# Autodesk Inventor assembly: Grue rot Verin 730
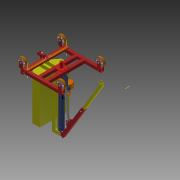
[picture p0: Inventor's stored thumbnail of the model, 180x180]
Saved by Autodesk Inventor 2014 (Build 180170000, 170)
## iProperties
Created: 2015-07
Part Number: Grue rot Verin 730
Document SubType Name: Assembly
Designer: OL
Author: OL
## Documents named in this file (29)
- D:\Lycée Larmand\Profs\SUJET BAC EDPI ETC\ELABORATION SUJET EDPI\Bourgeois RT 510\Modele Grue rotative\Grue rot Verin 730.iam
- D:\Lycée Larmand\Profs\SUJET BAC EDPI ETC\ELABORATION SUJET EDPI\Bourgeois RT 510\Modele Grue rotative\Cadre chariot.ipt
- D:\Lycée Larmand\Profs\SUJET BAC EDPI ETC\ELABORATION SUJET EDPI\Bourgeois RT 510\Modele Grue rotative\Axe.ipt
- D:\Lycée Larmand\Profs\SUJET BAC EDPI ETC\ELABORATION SUJET EDPI\Bourgeois RT 510\Modele Grue rotative\Poteau central.ipt
- D:\Lycée Larmand\Profs\SUJET BAC EDPI ETC\ELABORATION SUJET EDPI\Bourgeois RT 510\Modele Grue rotative\Potence pivot.ipt
- D:\Lycée Larmand\Profs\SUJET BAC EDPI ETC\ELABORATION SUJET EDPI\Bourgeois RT 510\Modele Grue rotative\Potence coulissante.ipt
- D:\Lycée Larmand\Profs\SUJET BAC EDPI ETC\ELABORATION SUJET EDPI\Bourgeois RT 510\Modele Grue rotative\Contrepoids.ipt
- D:\Lycée Larmand\Profs\SUJET BAC EDPI ETC\ELABORATION SUJET EDPI\Bourgeois RT 510\Modele Grue rotative\pompe\Pompe.ipt
- D:\Lycée Larmand\Profs\SUJET BAC EDPI ETC\ELABORATION SUJET EDPI\Bourgeois RT 510\Modele Grue rotative\Verin630-5-corps.ipt
- D:\Lycée Larmand\Profs\SUJET BAC EDPI ETC\ELABORATION SUJET EDPI\Bourgeois RT 510\Modele Grue rotative\Verin630-5-tige.ipt
- D:\Lycée Larmand\Profs\SUJET BAC EDPI ETC\ELABORATION SUJET EDPI\Bourgeois RT 510\Modele Grue rotative\Roue.ipt
- D:\Lycée Larmand\Profs\SUJET BAC EDPI ETC\ELABORATION SUJET EDPI\Bourgeois RT 510\Modele Grue rotative\Pivot de Direction.ipt
- D:\Lycée Larmand\Profs\SUJET BAC EDPI ETC\ELABORATION SUJET EDPI\Bourgeois RT 510\Modele Grue rotative\Palier de roue.ipt
- D:\Lycée Larmand\Profs\SUJET BAC EDPI ETC\ELABORATION SUJET EDPI\Bourgeois RT 510\Modele Grue rotative\Biellette.ipt
- D:\Lycée Larmand\Profs\SUJET BAC EDPI ETC\ELABORATION SUJET EDPI\Bourgeois RT 510\Modele Grue rotative\Vis H M10x20_02.ipt
- D:\Lycée Larmand\Profs\SUJET BAC EDPI ETC\ELABORATION SUJET EDPI\Bourgeois RT 510\Modele Grue rotative\Ecrou H M10x20_01.ipt
- D:\Lycée Larmand\Profs\SUJET BAC EDPI ETC\ELABORATION SUJET EDPI\Bourgeois RT 510\Modele Grue rotative\Axe D20.ipt
- D:\Lycée Larmand\Profs\SUJET BAC EDPI ETC\ELABORATION SUJET EDPI\Bourgeois RT 510\Modele Grue rotative\Goupille D20.ipt
- D:\Lycée Larmand\Profs\SUJET BAC EDPI ETC\ELABORATION SUJET EDPI\Bourgeois RT 510\Modele Grue rotative\Axe D20 L122.ipt
- D:\Lycée Larmand\Profs\SUJET BAC EDPI ETC\ELABORATION SUJET EDPI\Bourgeois RT 510\Modele Grue rotative\Rondelle d'appui D20.ipt
- D:\Lycée Larmand\Profs\SUJET BAC EDPI ETC\ELABORATION SUJET EDPI\Bourgeois RT 510\Modele Grue rotative\Axe D20 L96.ipt
- D:\Lycée Larmand\Profs\SUJET BAC EDPI ETC\ELABORATION SUJET EDPI\Bourgeois RT 510\Modele Grue rotative\Axe Roue D25 L116.ipt
- D:\Lycée Larmand\Profs\SUJET BAC EDPI ETC\ELABORATION SUJET EDPI\Bourgeois RT 510\Modele Grue rotative\Rondelle d'appui D25.ipt
- D:\Lycée Larmand\Profs\SUJET BAC EDPI ETC\ELABORATION SUJET EDPI\Bourgeois RT 510\Modele Grue rotative\Goupille D25.ipt
- D:\Lycée Larmand\Profs\SUJET BAC EDPI ETC\ELABORATION SUJET EDPI\Bourgeois RT 510\Modele Grue rotative\Butée manuelle.ipt
- D:\Lycée Larmand\Profs\SUJET BAC EDPI ETC\ELABORATION SUJET EDPI\Bourgeois RT 510\Modele Grue rotative\Goupille Cavalier.ipt
- D:\Lycée Larmand\Profs\SUJET BAC EDPI ETC\ELABORATION SUJET EDPI\Bourgeois RT 510\Modele Grue rotative\Bague d'arrêt D25.ipt
- D:\Lycée Larmand\Profs\SUJET BAC EDPI ETC\ELABORATION SUJET EDPI\Bourgeois RT 510\Modele Grue rotative\tuyau 1.ipt
- D:\Lycée Larmand\Profs\SUJET BAC EDPI ETC\ELABORATION SUJET EDPI\Bourgeois RT 510\Modele Grue rotative\tuyau 2.ipt
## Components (72 placed, 28 different names)
1. Cadre chariot:1 — Logement:1, Logement:9, Logement:10, Logement:12, Logement:13, Angle:1, Logement:37, Angle:12, Logement:38, Logement:39, Logement:42, Angle:15, Logement:43, Logement:44, Angle:16, Angle:17, Logement:54, Logement:74, Logement:75
2. Axe:1 — Logement:1, Logement:2
3. Poteau central:1 — Logement:2, Logement:3, Logement:4, Placage:3, Logement:5, Logement:6, Logement:7, Logement:21, Logement:22, Angle:3, Angle:6, Angle:7, Logement:27, Logement:28, Logement:57, Angle:20, Angle:22, Logement:58, Logement:60, Angle:24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
4. Potence pivot:1 — Logement:3, Placage:1, Placage:2, Placage:11, Logement:32, Angle:9, Logement:33, Logement:34, Logement:62, Angle:28
5. Potence coulissante:1 — Placage:1, Placage:2, Tangente:3
6. Contrepoids:1 — Logement:4, Placage:3, Angle:1, Angle:2, Logement:25, Logement:30, Logement:31
7. Pompe:1 — Logement:5, Logement:6, Logement:20, Logement:56, Angle:21, Angle:23, Logement:59, Logement:61, Angle:26, Angle:27, Logement:72
8. Verin630-5-corps:1 — Logement:7, Placage:4, Logement:73
9. Verin630-5-tige:1 — Placage:4, Placage:10
10. Roue:1 — Logement:9
11. Roue:2 — Logement:10
12. Pivot de Direction:1 — Logement:54, Logement:63, Angle:30, Angle:31, Placage:19, Placage:20
13. Palier de roue:1 — Logement:12, Logement:17, Logement:18, Placage:6, Angle:19, Logement:49, Logement:50, Logement:53, Placage:17, Angle:33
14. Palier de roue:2 — Logement:13, Logement:19, Angle:2, Placage:5, Logement:47, Angle:18, Logement:51, Logement:52, Logement:55, Placage:18, Angle:32
15. Biellette:1 — Logement:17, Placage:14, Logement:64, Logement:70
16. Biellette:2 — Logement:55, Placage:13, Logement:65, Logement:68
17. Roue:3 — Logement:18
18. Roue:4 — Logement:19
19. Vis H M10x20_02:1 — Logement:20, Angle:23
20. Ecrou H M10x20_01:1 — Logement:21, Angle:22
21. Axe D20:1 — Logement:22, Angle:3, Logement:23, Angle:4, Logement:24, Angle:5, Placage:24
22. Goupille D20:1 — Logement:24, Angle:5
23. Goupille D20:2 — Logement:23, Angle:4
24. Goupille D20:3 — Logement:26, Angle:7
25. Goupille D20:4 — Logement:29, Angle:8
26. Axe D20 L122:1 — Logement:25, Logement:26, Angle:6, Logement:29, Angle:8
27. Rondelle d'appui D20:1 — Logement:27
28. Rondelle d'appui D20:2 — Logement:28
29. Rondelle d'appui D20:3 — Logement:30
30. Rondelle d'appui D20:4 — Logement:31
31. Axe D20 L96:1 — Logement:32, Angle:9, Logement:35, Angle:10, Logement:36, Angle:11, Placage:23
32. Rondelle d'appui D20:5 — Logement:34
33. Rondelle d'appui D20:6 — Logement:33
34. Goupille D20:5 — Logement:35, Angle:10
35. Goupille D20:6 — Logement:36, Angle:11
36. Axe Roue D25 L116:1 — Logement:37, Angle:12, Angle:13, Angle:14
37. Rondelle d'appui D25:1 — Logement:38, Logement:41
38. Rondelle d'appui D25:2 — Logement:39, Logement:40
39. Goupille D25:1 — Logement:41, Angle:14
40. Goupille D25:2 — Logement:40, Angle:13
41. Axe Roue D25 L116:2 — Logement:42, Angle:15
42. Rondelle d'appui D25:3 — Logement:44, Logement:45
43. Rondelle d'appui D25:4 — Logement:43, Logement:46
44. Goupille D25:3 — Logement:45, Angle:16
45. Goupille D25:4 — Logement:46, Angle:17
46. Axe Roue D25 L116:3 — Logement:47, Angle:18
47. Axe Roue D25 L116:4 — Angle:19, Logement:53
48. Rondelle d'appui D25:5 — Logement:49
49. Rondelle d'appui D25:6 — Logement:50
50. Rondelle d'appui D25:7 — Logement:52
51. Rondelle d'appui D25:8 — Logement:51
52. Vis H M10x20_02:2 — Logement:56, Angle:21
53. Ecrou H M10x20_01:2 — Logement:57, Angle:20
54. Vis H M10x20_02:3 — Logement:59, Angle:26
55. Ecrou H M10x20_01:3 — Logement:58, Angle:24
56. Vis H M10x20_02:4 — Logement:61, Angle:27
57. Ecrou H M10x20_01:4 — Logement:60, Angle:25
58. Butée manuelle:1 — Logement:62, Angle:28, Placage:15, Affleurement:1, Angle:29, Tangente:3
59. Goupille Cavalier:1 — Placage:16, Affleurement:1, Angle:29
60. Bague d'arrêt D25:1 — Logement:63
61. Rondelle d'appui D20:7 — Logement:65, Logement:66, Placage:22
62. Rondelle d'appui D20:8 — Logement:64, Logement:67
63. Goupille D20:7 — Logement:66, Angle:30
64. Goupille D20:8 — Logement:67, Angle:31
65. Goupille D20:9 — Logement:69, Angle:32
66. Rondelle d'appui D20:9 — Logement:68, Logement:69
67. Rondelle d'appui D20:10 — Logement:70, Logement:71
68. Goupille D20:10 — Logement:71, Angle:33
69. tuyau 1:1 — Logement:72, Tangente:2
70. tuyau 2:1 — Logement:73, Tangente:2
71. Bague d'arrêt D25:2 — Logement:74
72. Bague d'arrêt D25:3 — Logement:75
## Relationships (124: Insert 69, Angle 33, Mate 19, Tangent 2, Flush 1)
- Logement:1 [Insert]: Cadre chariot:1 ↔ Axe:1
- Logement:2 [Insert]: Axe:1 ↔ Poteau central:1
- Logement:3 [Insert]: Poteau central:1 ↔ Potence pivot:1
- Placage:1 [Mate]: Potence pivot:1 ↔ Potence coulissante:1
- Placage:2 [Mate]: Potence pivot:1 ↔ Potence coulissante:1
- Logement:4 [Insert]: Poteau central:1 ↔ Contrepoids:1
- Placage:3 [Mate]: Poteau central:1 ↔ Contrepoids:1
- Logement:5 [Insert]: Poteau central:1 ↔ Pompe:1
- Logement:6 [Insert]: Poteau central:1 ↔ Pompe:1
- Logement:7 [Insert]: Poteau central:1 ↔ Verin630-5-corps:1
- Placage:4 [Mate]: Verin630-5-corps:1 ↔ Verin630-5-tige:1
- Logement:9 [Insert]: Cadre chariot:1 ↔ Roue:1
- Logement:10 [Insert]: Cadre chariot:1 ↔ Roue:2
- Logement:12 [Insert]: Cadre chariot:1 ↔ Palier de roue:1
- Logement:13 [Insert]: Cadre chariot:1 ↔ Palier de roue:2
- Logement:17 [Insert]: Palier de roue:1 ↔ Biellette:1
- Logement:18 [Insert]: Palier de roue:1 ↔ Roue:3
- Logement:19 [Insert]: Palier de roue:2 ↔ Roue:4
- Angle:1: Cadre chariot:1 ↔ Contrepoids:1
- Angle:2: Contrepoids:1 ↔ Palier de roue:2
- Placage:5 [Mate]: Palier de roue:2
- Placage:6 [Mate]: Palier de roue:1
- Logement:20 [Insert]: Pompe:1 ↔ Vis H M10x20_02:1
- Logement:21 [Insert]: Poteau central:1 ↔ Ecrou H M10x20_01:1
- Logement:22 [Insert]: Poteau central:1 ↔ Axe D20:1
- Angle:3: Poteau central:1 ↔ Axe D20:1
- Logement:23 [Insert]: Axe D20:1 ↔ Goupille D20:2
- Angle:4: Axe D20:1 ↔ Goupille D20:2
- Logement:24 [Insert]: Axe D20:1 ↔ Goupille D20:1
- Angle:5: Axe D20:1 ↔ Goupille D20:1
- Placage:10 [Mate]: Verin630-5-tige:1
- Placage:11 [Mate]: Potence pivot:1
- Logement:25 [Insert]: Contrepoids:1 ↔ Axe D20 L122:1
- Logement:26 [Insert]: Goupille D20:3 ↔ Axe D20 L122:1
- Angle:6: Poteau central:1 ↔ Axe D20 L122:1
- Angle:7: Poteau central:1 ↔ Goupille D20:3
- Logement:27 [Insert]: Poteau central:1 ↔ Rondelle d'appui D20:1
- Logement:28 [Insert]: Poteau central:1 ↔ Rondelle d'appui D20:2
- Logement:29 [Insert]: Goupille D20:4 ↔ Axe D20 L122:1
- Angle:8: Goupille D20:4 ↔ Axe D20 L122:1
- Logement:30 [Insert]: Contrepoids:1 ↔ Rondelle d'appui D20:3
- Logement:31 [Insert]: Contrepoids:1 ↔ Rondelle d'appui D20:4
- Logement:32 [Insert]: Potence pivot:1 ↔ Axe D20 L96:1
- Angle:9: Potence pivot:1 ↔ Axe D20 L96:1
- Logement:33 [Insert]: Potence pivot:1 ↔ Rondelle d'appui D20:6
- Logement:34 [Insert]: Potence pivot:1 ↔ Rondelle d'appui D20:5
- Logement:35 [Insert]: Axe D20 L96:1 ↔ Goupille D20:5
- Angle:10: Axe D20 L96:1 ↔ Goupille D20:5
- Logement:36 [Insert]: Axe D20 L96:1 ↔ Goupille D20:6
- Angle:11: Axe D20 L96:1 ↔ Goupille D20:6
- Logement:37 [Insert]: Cadre chariot:1 ↔ Axe Roue D25 L116:1
- Angle:12: Cadre chariot:1 ↔ Axe Roue D25 L116:1
- Logement:38 [Insert]: Cadre chariot:1 ↔ Rondelle d'appui D25:1
- Logement:39 [Insert]: Cadre chariot:1 ↔ Rondelle d'appui D25:2
- Logement:40 [Insert]: Rondelle d'appui D25:2 ↔ Goupille D25:2
- Angle:13: Axe Roue D25 L116:1 ↔ Goupille D25:2
- Logement:41 [Insert]: Rondelle d'appui D25:1 ↔ Goupille D25:1
- Angle:14: Axe Roue D25 L116:1 ↔ Goupille D25:1
- Logement:42 [Insert]: Cadre chariot:1 ↔ Axe Roue D25 L116:2
- Angle:15: Cadre chariot:1 ↔ Axe Roue D25 L116:2
- Logement:43 [Insert]: Cadre chariot:1 ↔ Rondelle d'appui D25:4
- Logement:44 [Insert]: Cadre chariot:1 ↔ Rondelle d'appui D25:3
- Logement:45 [Insert]: Rondelle d'appui D25:3 ↔ Goupille D25:3
- Angle:16: Cadre chariot:1 ↔ Goupille D25:3
- Logement:46 [Insert]: Rondelle d'appui D25:4 ↔ Goupille D25:4
- Angle:17: Cadre chariot:1 ↔ Goupille D25:4
- Logement:47 [Insert]: Palier de roue:2 ↔ Axe Roue D25 L116:3
- Angle:18: Palier de roue:2 ↔ Axe Roue D25 L116:3
- Angle:19: Palier de roue:1 ↔ Axe Roue D25 L116:4
- Logement:49 [Insert]: Palier de roue:1 ↔ Rondelle d'appui D25:5
- Logement:50 [Insert]: Palier de roue:1 ↔ Rondelle d'appui D25:6
- Logement:51 [Insert]: Palier de roue:2 ↔ Rondelle d'appui D25:8
- Logement:52 [Insert]: Palier de roue:2 ↔ Rondelle d'appui D25:7
- Logement:53 [Insert]: Palier de roue:1 ↔ Axe Roue D25 L116:4
- Logement:54 [Insert]: Cadre chariot:1 ↔ Pivot de Direction:1
- Logement:55 [Insert]: Palier de roue:2 ↔ Biellette:2
- Placage:13 [Mate]: Biellette:2
- Placage:14 [Mate]: Biellette:1
- Logement:56 [Insert]: Pompe:1 ↔ Vis H M10x20_02:2
- Logement:57 [Insert]: Poteau central:1 ↔ Ecrou H M10x20_01:2
- Angle:20: Poteau central:1 ↔ Ecrou H M10x20_01:2
- Angle:21: Pompe:1 ↔ Vis H M10x20_02:2
- Angle:22: Poteau central:1 ↔ Ecrou H M10x20_01:1
- Angle:23: Pompe:1 ↔ Vis H M10x20_02:1
- Logement:58 [Insert]: Poteau central:1 ↔ Ecrou H M10x20_01:3
- Logement:59 [Insert]: Pompe:1 ↔ Vis H M10x20_02:3
- Logement:60 [Insert]: Poteau central:1 ↔ Ecrou H M10x20_01:4
- Logement:61 [Insert]: Pompe:1 ↔ Vis H M10x20_02:4
- Angle:24: Poteau central:1 ↔ Ecrou H M10x20_01:3
- Angle:25: Poteau central:1 ↔ Ecrou H M10x20_01:4
- Angle:26: Pompe:1 ↔ Vis H M10x20_02:3
- Angle:27: Pompe:1 ↔ Vis H M10x20_02:4
- Logement:62 [Insert]: Potence pivot:1 ↔ Butée manuelle:1
- Angle:28: Potence pivot:1 ↔ Butée manuelle:1
- Placage:15 [Mate]: Butée manuelle:1
- Placage:16 [Mate]: Goupille Cavalier:1
- Affleurement:1 [Flush]: Butée manuelle:1 ↔ Goupille Cavalier:1
- Angle:29: Butée manuelle:1 ↔ Goupille Cavalier:1
- Logement:63 [Insert]: Pivot de Direction:1 ↔ Bague d'arrêt D25:1
- Logement:64 [Insert]: Biellette:1 ↔ Rondelle d'appui D20:8
- Logement:65 [Insert]: Biellette:2 ↔ Rondelle d'appui D20:7
- Logement:66 [Insert]: Rondelle d'appui D20:7 ↔ Goupille D20:7
- Angle:30: Pivot de Direction:1 ↔ Goupille D20:7
- Logement:67 [Insert]: Rondelle d'appui D20:8 ↔ Goupille D20:8
- Angle:31: Pivot de Direction:1 ↔ Goupille D20:8
- Placage:17 [Mate]: Palier de roue:1
- Placage:18 [Mate]: Palier de roue:2
- Placage:19 [Mate]: Pivot de Direction:1
- Placage:20 [Mate]: Pivot de Direction:1
- Placage:22 [Mate]: Rondelle d'appui D20:7
- Logement:68 [Insert]: Biellette:2 ↔ Rondelle d'appui D20:9
- Logement:69 [Insert]: Goupille D20:9 ↔ Rondelle d'appui D20:9
- Angle:32: Palier de roue:2 ↔ Goupille D20:9
- Logement:70 [Insert]: Biellette:1 ↔ Rondelle d'appui D20:10
- Logement:71 [Insert]: Rondelle d'appui D20:10 ↔ Goupille D20:10
- Angle:33: Palier de roue:1 ↔ Goupille D20:10
- Logement:72 [Insert]: Pompe:1 ↔ tuyau 1:1
- Logement:73 [Insert]: Verin630-5-corps:1 ↔ tuyau 2:1
- Tangente:2: tuyau 1:1 ↔ tuyau 2:1
- Logement:74 [Insert]: Cadre chariot:1 ↔ Bague d'arrêt D25:2
- Logement:75 [Insert]: Cadre chariot:1 ↔ Bague d'arrêt D25:3
- Placage:23 [Mate]: Axe D20 L96:1
- Placage:24 [Mate]: Axe D20:1
- Tangente:3: Potence coulissante:1 ↔ Butée manuelle:1
